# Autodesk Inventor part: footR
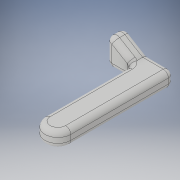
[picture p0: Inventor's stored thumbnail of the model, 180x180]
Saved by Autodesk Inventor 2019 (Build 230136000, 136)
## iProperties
Created: 2020-09
Part Number: footR
Material: 一般
Document SubType Name: Modeling
Designer: kikut
Density: 1 g/cm^3
Appearance: 既定
Author: kikut
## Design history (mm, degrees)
sketch "スケッチ1"
  geometry: L1 (-0.005, -0.08)-(0.005, -0.08); L2 (0.005, -0.08)-(0.005, -0.04); L3 (0.005, -0.04)-(-0.005, -0.04); L4 (-0.005, -0.04)-(-0.005, -0.08); L5 (-0.005, -0.08)-(0.005, -0.04); L6 (0.005, -0.08)-(-0.005, -0.04); L7 (0, -0.096)-(0, 0.016) reference; A1 r 0.005 centre (0, -0.04) between (0.005, -0.04) and (-0.005, -0.04); 2 further points
  constraints: 12 end point, 4 midpoint, 2 parallel, 2 point on circle, 1 centre point, 1 horizontal, 1 perpendicular, 1 other
  dimensions: "d0" = 0.04 distance of L1.end L2.end; "d1" = 0.04 distance from line of L3 point (0, 0); "d2" = 0.01 distance of L2.end L3.end
extrude "押し出し1" new body sketch "スケッチ1" stored distance "d3" = 0.006; taper "d4" = 0 deg
sketch "スケッチ4"
  geometry: L1 (0, -0.006)-(0.01, -0.006) reference; L2 (0.01, -0.006)-(0.02, -0.006); L3 (0.02, -0.006)-(0.02, 0.006); L4 (0.01, 0)-(0, 0) reference; L5 (0.02, 0.006)-(0.01, 0); L6 (0.01, 0)-(0.01, -0.006); 1 further point
  constraints: 8 end point, 1 horizontal, 1 parallel, 1 perpendicular
  dimensions: "d17" = 0.01 distance of L1.end L2.end; "d18" = 0.012 distance of L2.end L3.end
extrude "押し出し4" join sketch "スケッチ4" distance "d19" = 0.006; taper "d20" = 0 deg
fillet "フィレット5" dims "d21" = 0.002
fillet "フィレット6" dims "d22" = 0.002
fillet "フィレット7" dims "d23" = 0.002
node "ソリッド1"
